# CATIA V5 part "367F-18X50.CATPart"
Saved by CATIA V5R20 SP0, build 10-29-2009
Part number: 367F-18X50
Definition: NONE
Nomenclature: 367F-18X50
Source: Unknown
Description: 367F-18X50
Bounding box of the stored display mesh (mm): x 0 to 50, y -14 to 14, z -14 to 14
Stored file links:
  C:\Users\Utente\Desktop\IO LAVORO\3D X SITO CF\X SITO\PLASTICA\3D files 367\367F-18X50.CATPart
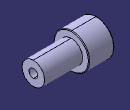
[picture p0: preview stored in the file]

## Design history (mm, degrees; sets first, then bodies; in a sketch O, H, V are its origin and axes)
Body1 "367F-18X50" (main body)
  Solid1: solid without history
